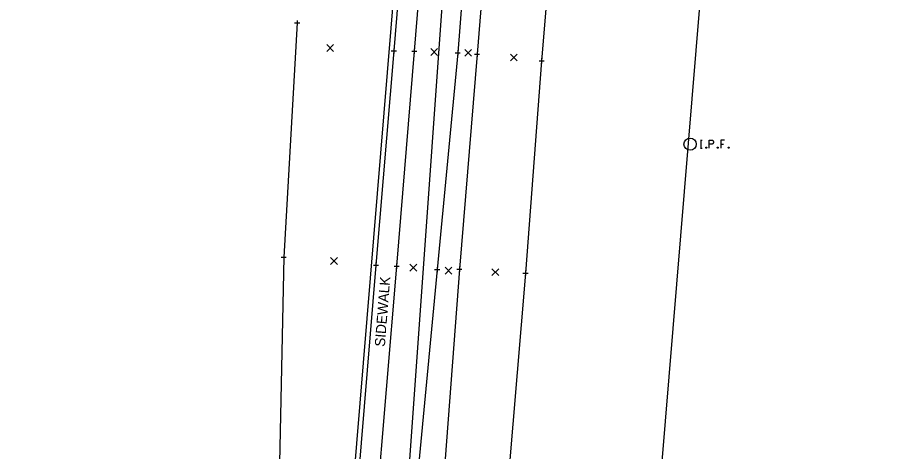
# Model space of a CAD drawing. Extents: x 1380550 to 1381945, y 468927 to 470496.
# Drawn here: x 1381495.3 to 1381668.4, y 469893 to 469978.3 of the extents above; entities that cross this region are included whole.
import ezdxf

# ---------------------------------------------------------------- set-up
doc = ezdxf.new("R2010")
doc.units = 0
for name, color, linetype in [('DR_X_Ditch', 7, 'Continuous'), ('PV_X_COP', 7, 'Continuous'), ('PV_X_EOP', 7, 'Continuous'), ('PV_X_Walk', 7, 'Continuous'), ('RD_X_Text', 7, 'Continuous'), ('RW_X_Esmt_General', 7, 'Continuous'), ('SV_X_Mon_Cells_Found', 7, 'Continuous'), ('SV_X_Random_Point', 7, 'Continuous'), ('SV_X_Shot_Marker', 7, 'Continuous'), ('UT_X_Electric', 7, 'Continuous'), ('UT_X_Telecom', 7, 'Continuous')]:
    doc.layers.add(name, color=color, linetype=linetype)

msp = doc.modelspace()

# ---------------------------------------------------------------- linework, layer by layer
at = {"layer": 'DR_X_Ditch'}
msp.add_lwpolyline([(1381599.49, 470202.78), (1381597.12, 470179.51), (1381597.25, 470175.53), (1381597.2, 470175.03), (1381592.57, 470125.52), (1381589.1, 470072.43), (1381585.65, 470022.01), (1381581.71, 469971.4), (1381577.66, 469928.75), (1381573.1, 469880.44), (1381570.64, 469867.29)], dxfattribs=at)
at = {"layer": 'PV_X_COP'}
msp.add_lwpolyline([(1381627.41, 470324.23), (1381625.02, 470294.42), (1381622.34, 470259.95), (1381618.76, 470220.14), (1381616.92, 470200.19), (1381615.1, 470178.83), (1381610.95, 470124.78), (1381606.49, 470071.23), (1381602.26, 470019.36), (1381598.18, 469969.8), (1381595.01, 469928.06), (1381590.91, 469878.81), (1381589.36, 469859.11), (1381585.99, 469815.58), (1381581.29, 469760.78)], dxfattribs=at)
at = {"layer": 'PV_X_EOP'}
for points in [[(1381575.39, 470244.04), (1381576.99, 470244.17), (1381579.54, 470245.54), (1381580.63, 470247.96), (1381580.96, 470249.54), (1381591.47, 470243.59), (1381595.25, 470241), (1381599.72, 470235.67), (1381603.29, 470229.19), (1381604.88, 470222.31), (1381604.1, 470201.73), (1381602.36, 470179.43), (1381598.63, 470125.51), (1381593.59, 470071.89), (1381589.53, 470020.65), (1381585.49, 469971.09), (1381582.04, 469928.84), (1381578.38, 469880.28), (1381576.86, 469862.02), (1381576.83, 469860.71), (1381576.16, 469857.38), (1381571.59, 469847.12), (1381563.14, 469838.25)], [(1381550.16, 469977.26), (1381547.52, 469931.2), (1381546.52, 469881.36), (1381546.07, 469867.59), (1381545.21, 469852.93)]]:
    msp.add_lwpolyline(points, dxfattribs=at)
at = {"layer": 'PV_X_Walk'}
for points in [[(1381595.25, 470241), (1381595.01, 470239.38), (1381594.79, 470235.56), (1381591.94, 470203.13), (1381590.15, 470180.15), (1381585.84, 470126.11), (1381581.45, 470072.84), (1381577.22, 470021.47), (1381573.16, 469971.68), (1381569.7, 469929.43), (1381565.6, 469880.89), (1381564.41, 469867), (1381562.95, 469848.39), (1381561.9, 469840.88)], [(1381542.56, 470237.64), (1381568.34, 470236.69), (1381578.51, 470236.26), (1381584.49, 470236.02), (1381590.64, 470235.62), (1381587.95, 470203.42), (1381586.62, 470180.46), (1381581.93, 470126.46), (1381577.65, 470073.24), (1381573.2, 470021.54), (1381569.15, 469971.74), (1381565.64, 469929.65), (1381561.64, 469881.16), (1381560.46, 469867.32), (1381559.27, 469848.71), (1381558.35, 469840.14)]]:
    msp.add_lwpolyline(points, dxfattribs=at)
at = {"layer": 'RW_X_Esmt_General'}
for points in [[(1381490.4, 469029.46), (1381590.2, 470237.18), (1380558.69, 470277.03)], [(1381783.19, 470213.89), (1381648.78, 470217.49), (1381563.79, 469189.03)]]:
    msp.add_lwpolyline(points, dxfattribs=at)
at = {"layer": 'SV_X_Mon_Cells_Found'}
for points in [[(1381629.36, 469954.22), (1381629.71, 469954.22)], [(1381629.53, 469952.62), (1381629.53, 469954.22)], [(1381631.1, 469952.62), (1381631.1, 469954.22), (1381631.63, 469954.22), (1381631.68, 469954.21), (1381631.76, 469954.18), (1381631.79, 469954.16), (1381631.83, 469954.13), (1381631.87, 469954.07), (1381631.9, 469954.01), (1381631.92, 469953.91), (1381631.92, 469953.75), (1381631.91, 469953.7), (1381631.89, 469953.63), (1381631.85, 469953.54), (1381631.8, 469953.5), (1381631.77, 469953.48), (1381631.72, 469953.45), (1381631.63, 469953.44), (1381631.1, 469953.44)], [(1381634.11, 469954.22), (1381633.35, 469954.22), (1381633.35, 469952.62)], [(1381629.36, 469952.62), (1381629.71, 469952.62)], [(1381630.49, 469952.84), (1381630.55, 469952.84), (1381630.58, 469952.81), (1381630.61, 469952.76), (1381630.61, 469952.7), (1381630.58, 469952.65), (1381630.55, 469952.62), (1381630.49, 469952.62), (1381630.46, 469952.65), (1381630.43, 469952.7), (1381630.43, 469952.76), (1381630.46, 469952.81), (1381630.49, 469952.84)], [(1381632.74, 469952.84), (1381632.8, 469952.84), (1381632.83, 469952.81), (1381632.86, 469952.76), (1381632.86, 469952.7), (1381632.83, 469952.65), (1381632.8, 469952.62), (1381632.74, 469952.62), (1381632.71, 469952.65), (1381632.67, 469952.7), (1381632.67, 469952.76), (1381632.71, 469952.81), (1381632.74, 469952.84)], [(1381633.35, 469953.44), (1381633.89, 469953.44)], [(1381634.89, 469952.84), (1381634.94, 469952.84), (1381634.98, 469952.81), (1381635.01, 469952.76), (1381635.01, 469952.7), (1381634.98, 469952.65), (1381634.94, 469952.62), (1381634.89, 469952.62), (1381634.86, 469952.65), (1381634.82, 469952.7), (1381634.82, 469952.76), (1381634.86, 469952.81), (1381634.89, 469952.84)]]:
    msp.add_lwpolyline(points, dxfattribs=at)
msp.add_circle((1381627.34, 469953.42), 1.2, dxfattribs=at)
at = {"layer": 'SV_X_Random_Point'}
for p, q in [((1381555.99, 469971.67), (1381557.33, 469973.01)), ((1381555.99, 469973.01), (1381557.33, 469971.67)), ((1381576.42, 469970.87), (1381577.75, 469972.2)), ((1381576.42, 469972.2), (1381577.75, 469970.87)), ((1381583.09, 469970.7), (1381584.43, 469972.04)), ((1381583.09, 469972.04), (1381584.43, 469970.7)), ((1381592.06, 469969.78), (1381593.39, 469971.11)), ((1381592.06, 469971.11), (1381593.39, 469969.78)), ((1381556.74, 469929.76), (1381558.07, 469931.1)), ((1381556.74, 469931.1), (1381558.07, 469929.76)), ((1381572.32, 469928.46), (1381573.66, 469929.79)), ((1381572.32, 469929.79), (1381573.66, 469928.46)), ((1381579.24, 469927.88), (1381580.57, 469929.21)), ((1381579.24, 469929.21), (1381580.57, 469927.88)), ((1381588.43, 469927.56), (1381589.76, 469928.89)), ((1381588.43, 469928.89), (1381589.76, 469927.56))]:
    msp.add_line(p, q, dxfattribs=at)
at = {"layer": 'SV_X_Shot_Marker'}
for p, q in [((1381550.16, 469977.76), (1381550.16, 469976.76)), ((1381549.66, 469977.26), (1381550.66, 469977.26)), ((1381550.16, 469977.26), (1381550.16, 469977.26)), ((1381568.65, 469971.74), (1381569.65, 469971.74)), ((1381569.15, 469972.24), (1381569.15, 469971.24)), ((1381569.15, 469971.74), (1381569.15, 469971.74)), ((1381572.66, 469971.68), (1381573.66, 469971.68)), ((1381573.16, 469972.18), (1381573.16, 469971.18)), ((1381573.16, 469971.68), (1381573.16, 469971.68)), ((1381581.21, 469971.4), (1381582.21, 469971.4)), ((1381581.71, 469971.9), (1381581.71, 469970.9)), ((1381581.71, 469971.4), (1381581.71, 469971.4)), ((1381584.99, 469971.09), (1381585.99, 469971.09)), ((1381585.49, 469971.59), (1381585.49, 469970.59)), ((1381585.49, 469971.09), (1381585.49, 469971.09)), ((1381597.68, 469969.8), (1381598.68, 469969.8)), ((1381598.18, 469970.3), (1381598.18, 469969.3)), ((1381598.18, 469969.8), (1381598.18, 469969.8)), ((1381547.02, 469931.2), (1381548.02, 469931.2)), ((1381547.52, 469931.7), (1381547.52, 469930.7)), ((1381547.52, 469931.2), (1381547.52, 469931.2)), ((1381565.14, 469929.65), (1381566.14, 469929.65)), ((1381565.64, 469930.15), (1381565.64, 469929.15)), ((1381565.64, 469929.65), (1381565.64, 469929.65)), ((1381569.2, 469929.43), (1381570.2, 469929.43)), ((1381569.7, 469929.93), (1381569.7, 469928.93)), ((1381569.7, 469929.43), (1381569.7, 469929.43)), ((1381577.66, 469929.25), (1381577.66, 469928.25)), ((1381582.04, 469929.34), (1381582.04, 469928.34)), ((1381577.16, 469928.75), (1381578.16, 469928.75)), ((1381577.66, 469928.75), (1381577.66, 469928.75)), ((1381581.54, 469928.84), (1381582.54, 469928.84)), ((1381582.04, 469928.84), (1381582.04, 469928.84)), ((1381594.51, 469928.06), (1381595.51, 469928.06)), ((1381595.01, 469928.56), (1381595.01, 469927.56)), ((1381595.01, 469928.06), (1381595.01, 469928.06))]:
    msp.add_line(p, q, dxfattribs=at)
at = {"layer": 'UT_X_Electric'}
msp.add_lwpolyline([(1381665.56, 470247.4), (1381595.79, 470220.83), (1381581.26, 470018.2), (1381571.97, 469887.64), (1381559.77, 469757.41), (1381543.86, 469565.78), (1381529.17, 469390.12), (1381515.28, 469203.1), (1381540.8, 469054.26)], dxfattribs=at)
at = {"layer": 'UT_X_Telecom'}
msp.add_lwpolyline([(1381665.56, 470247.4), (1381595.35, 470217.51), (1381581.26, 470018.2), (1381571.97, 469887.64), (1381559.77, 469757.41), (1381543.86, 469565.78), (1381529.17, 469390.12), (1381515.28, 469203.1), (1381540.8, 469054.26)], dxfattribs=at)

# ---------------------------------------------------------------- texts
at = {"layer": 'RD_X_Text'}
msp.add_text('SIDEWALK', height=2, rotation=85.521, dxfattribs=at).set_placement((1381567.38, 469913.52))

doc.saveas('drawing.dxf')
